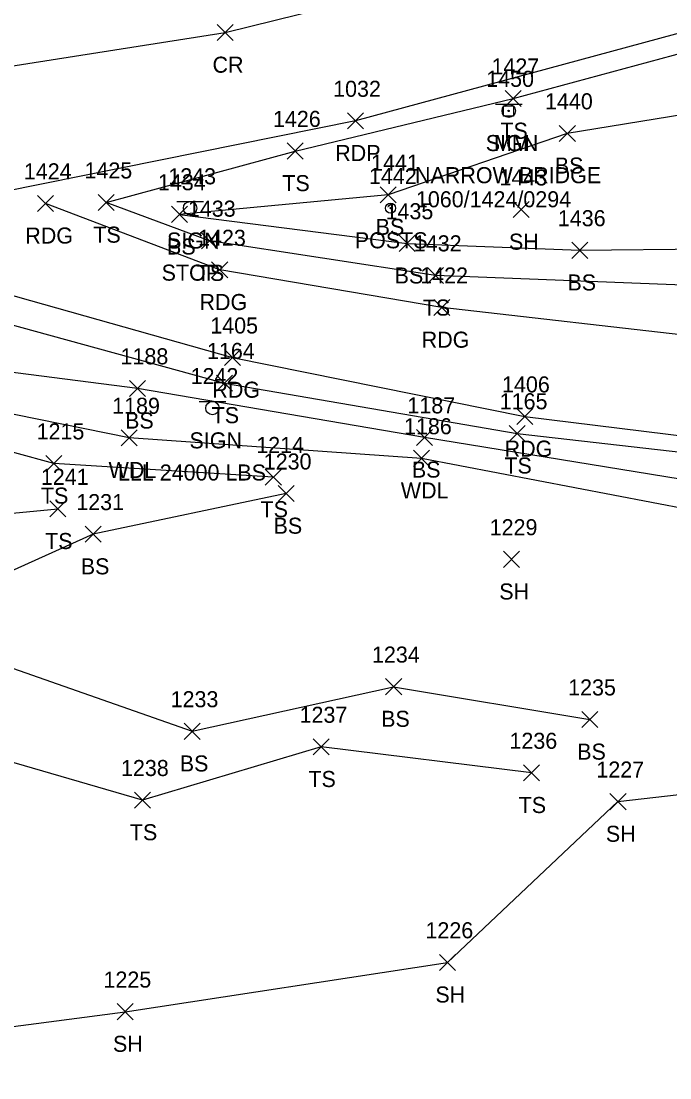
# Model space of a CAD drawing. Extents: x 1633660 to 1636532, y 388643 to 392631.
# Drawn here: x 1633994.3 to 1634075.1, y 388650.9 to 388782.5 of the extents above; entities that cross this region are included whole.
import ezdxf

# ---------------------------------------------------------------- set-up
doc = ezdxf.new("R2010")
doc.units = 0
for name, color, linetype in [('L_A', 7, 'Continuous'), ('L_I', 7, 'Continuous'), ('L_TIC', 7, 'Continuous'), ('LAWA', 7, 'Continuous'), ('LELB', 7, 'Continuous'), ('LPST', 7, 'Continuous'), ('LSOGP', 7, 'Continuous'), ('P_A', 7, 'Continuous'), ('P_I', 7, 'Continuous'), ('P_TIC', 7, 'Continuous'), ('PET', 7, 'Continuous'), ('PEU', 7, 'Continuous'), ('PRC', 7, 'Continuous'), ('S_A', 7, 'Continuous'), ('S_C', 7, 'Continuous'), ('S_I', 7, 'Continuous'), ('SRM', 7, 'Continuous'), ('SSGN', 7, 'Continuous')]:
    doc.layers.add(name, color=color, linetype=linetype)

msp = doc.modelspace()

# ---------------------------------------------------------------- linework, layer by layer
at = {"layer": 'L_TIC'}
for points in [[(1634054.55, 388771.84), (1634056.55, 388773.84)], [(1634056.55, 388771.84), (1634054.55, 388773.84)], [(1634061.3, 388767.5), (1634063.3, 388769.5)], [(1634063.3, 388767.5), (1634061.3, 388769.5)], [(1634027.39, 388765.31), (1634029.39, 388767.31)], [(1634029.39, 388765.31), (1634027.39, 388767.31)], [(1634038.99, 388759.86), (1634040.99, 388761.86)], [(1634040.99, 388759.86), (1634038.99, 388761.86)], [(1634003.85, 388758.89), (1634005.85, 388760.89)], [(1634005.85, 388758.89), (1634003.85, 388760.89)], [(1634013, 388757.42), (1634015, 388759.42)], [(1634015, 388757.42), (1634013, 388759.42)], [(1634055.54, 388758.02), (1634057.54, 388760.02)], [(1634057.54, 388758.02), (1634055.54, 388760.02)], [(1634016.74, 388754.13), (1634018.74, 388756.13)], [(1634018.74, 388754.13), (1634016.74, 388756.13)], [(1634041.35, 388753.81), (1634043.35, 388755.81)], [(1634043.35, 388753.81), (1634041.35, 388755.81)], [(1634062.87, 388752.94), (1634064.87, 388754.94)], [(1634064.87, 388752.94), (1634062.87, 388754.94)], [(1634044.88, 388749.81), (1634046.88, 388751.81)], [(1634046.88, 388749.81), (1634044.88, 388751.81)], [(1634018.59, 388736.41), (1634020.59, 388738.41)], [(1634020.59, 388736.41), (1634018.59, 388738.41)], [(1634007.78, 388735.74), (1634009.78, 388737.74)], [(1634009.78, 388735.74), (1634007.78, 388737.74)], [(1634006.74, 388729.58), (1634008.74, 388731.58)], [(1634008.74, 388729.58), (1634006.74, 388731.58)], [(1634043.5, 388729.63), (1634045.5, 388731.63)], [(1634045.5, 388729.63), (1634043.5, 388731.63)], [(1634055.05, 388730.14), (1634057.05, 388732.14)], [(1634057.05, 388730.14), (1634055.05, 388732.14)], [(1634043.14, 388727.03), (1634045.14, 388729.03)], [(1634045.14, 388727.03), (1634043.14, 388729.03)], [(1633997.33, 388726.39), (1633999.33, 388728.39)], [(1633999.33, 388726.39), (1633997.33, 388728.39)], [(1634024.68, 388724.69), (1634026.68, 388726.69)], [(1634026.68, 388724.69), (1634024.68, 388726.69)], [(1634026.27, 388722.64), (1634028.27, 388724.64)], [(1634028.27, 388722.64), (1634026.27, 388724.64)], [(1633997.85, 388720.73), (1633999.85, 388722.73)], [(1633999.85, 388720.73), (1633997.85, 388722.73)], [(1634002.26, 388717.58), (1634004.26, 388719.58)], [(1634004.26, 388717.58), (1634002.26, 388719.58)], [(1634054.33, 388714.45), (1634056.33, 388716.45)], [(1634056.33, 388714.45), (1634054.33, 388716.45)], [(1634039.67, 388698.59), (1634041.67, 388700.59)], [(1634041.67, 388698.59), (1634039.67, 388700.59)], [(1634064.09, 388694.5), (1634066.09, 388696.5)], [(1634066.09, 388694.5), (1634064.09, 388696.5)], [(1634014.59, 388693.03), (1634016.59, 388695.03)], [(1634016.59, 388693.03), (1634014.59, 388695.03)], [(1634030.65, 388691.09), (1634032.65, 388693.09)], [(1634032.65, 388691.09), (1634030.65, 388693.09)], [(1634056.83, 388687.85), (1634058.83, 388689.85)], [(1634058.83, 388687.85), (1634056.83, 388689.85)], [(1634008.4, 388684.46), (1634010.4, 388686.46)], [(1634010.4, 388684.46), (1634008.4, 388686.46)], [(1634067.61, 388684.27), (1634069.61, 388686.27)], [(1634069.61, 388684.27), (1634067.61, 388686.27)], [(1634046.38, 388664.25), (1634048.38, 388666.25)], [(1634048.38, 388664.25), (1634046.38, 388666.25)], [(1634006.22, 388658.11), (1634008.22, 388660.11)], [(1634008.22, 388658.11), (1634006.22, 388660.11)]]:
    msp.add_lwpolyline(points, dxfattribs=at)
at = {"layer": 'LAWA'}
msp.add_lwpolyline([(1634213.54, 388715.93), (1634181.29, 388718.06), (1634158.57, 388709.96), (1634132.08, 388702.35), (1634126.3, 388716.32), (1634107.18, 388718.38), (1634087.11, 388719.77), (1634044.14, 388728.03), (1634007.74, 388730.58), (1633979.24, 388736.34), (1633973.65, 388737.75)], dxfattribs=at)
at = {"layer": 'LELB'}
for points in [[(1634004.85, 388759.89), (1634028.39, 388766.31), (1634055.55, 388772.84), (1634087.81, 388781.56), (1634094.13, 388773.43), (1634095.58, 388760.67), (1634083.14, 388749.36), (1634045.88, 388750.81), (1634017.74, 388755.13)], [(1634014, 388758.42), (1634042.35, 388754.81), (1634063.87, 388753.94), (1634079.68, 388754.14), (1634090.31, 388767.38), (1634089.57, 388772.95), (1634062.3, 388768.5), (1634039.99, 388760.86)], [(1634039.99, 388760.86), (1634014, 388758.42)], [(1634017.74, 388755.13), (1634004.85, 388759.89)], [(1633929.25, 388734.22), (1633932.64, 388741.33), (1633934.84, 388748.14), (1633955.61, 388748.95), (1633990.07, 388745.5), (1634019.59, 388737.41), (1634056.05, 388731.14), (1634102.32, 388725.85), (1634131.53, 388723.22), (1634169.63, 388722.22), (1634213.51, 388722.74)], [(1634103.78, 388721.69), (1634089.59, 388723.27), (1634044.5, 388730.63), (1634008.78, 388736.74), (1633974.13, 388741.19), (1633971.98, 388741.19), (1633967.26, 388742.03), (1633963.35, 388743.2), (1633950.4, 388742.79), (1633939.89, 388743.26), (1633938.77, 388738.1), (1633951.99, 388740.33), (1633960.06, 388738.71)], [(1634025.68, 388725.69), (1633998.33, 388727.39), (1633974.03, 388734.05)], [(1634027.27, 388723.64), (1634003.26, 388718.58), (1633978, 388707.19), (1634015.59, 388694.03), (1634040.67, 388699.59), (1634065.09, 388695.5)], [(1633971.87, 388719.16), (1633998.85, 388721.73)], [(1634057.83, 388688.85), (1634031.65, 388692.09), (1634009.4, 388685.46), (1633973.11, 388696)]]:
    msp.add_lwpolyline(points, dxfattribs=at)
at = {"layer": 'LPST'}
for radius in [0.625, 0.0833]:
    msp.add_circle((1634040.29, 388759.19), radius, dxfattribs=at)
at = {"layer": 'LSOGP'}
msp.add_lwpolyline([(1633892.15, 388670.64), (1633924.06, 388658.35), (1633934.83, 388655.28), (1633940.09, 388658.82), (1633943.21, 388657.8), (1633944.44, 388650.87), (1634007.22, 388659.11), (1634047.38, 388665.25), (1634068.61, 388685.27), (1634091.13, 388687.87), (1634119.65, 388686.04), (1634149.89, 388685.18), (1634208.91, 388690.49), (1634214.85, 388708.43), (1634213.54, 388715.93), (1634213.47, 388720.91), (1634213.51, 388722.74), (1634213.85, 388724.5), (1634214.78, 388736.17), (1634218.98, 388740.85), (1634254.67, 388740.24)], dxfattribs=at)
at = {"layer": 'P_TIC'}
for points in [[(1634018.68, 388780.06), (1634020.68, 388782.06)], [(1634020.68, 388780.06), (1634018.68, 388782.06)], [(1634034.91, 388769.06), (1634036.91, 388771.06)], [(1634036.91, 388769.06), (1634034.91, 388771.06)], [(1633996.3, 388758.78), (1633998.3, 388760.78)], [(1633998.3, 388758.78), (1633996.3, 388760.78)], [(1634018, 388750.5), (1634020, 388752.5)], [(1634020, 388750.5), (1634018, 388752.5)], [(1634045.67, 388745.81), (1634047.67, 388747.81)], [(1634047.67, 388745.81), (1634045.67, 388747.81)], [(1634019.6, 388739.58), (1634021.6, 388741.58)], [(1634021.6, 388739.58), (1634019.6, 388741.58)], [(1634056, 388732.24), (1634058, 388734.24)], [(1634058, 388732.24), (1634056, 388734.24)]]:
    msp.add_lwpolyline(points, dxfattribs=at)
at = {"layer": 'PET'}
msp.add_lwpolyline([(1634233.66, 388838.29), (1634176.14, 388816.11), (1634127.42, 388797.4), (1634083.73, 388783.04), (1634035.91, 388770.06), (1633987.08, 388760.24), (1633936.49, 388754.34), (1633886.38, 388755.37), (1633827.16, 388754.09), (1633779.6, 388750.43), (1633734.35, 388742.35), (1633709.35, 388735.6), (1633689.74, 388728.83)], dxfattribs=at)
at = {"layer": 'PEU'}
for points in [[(1634091.6, 388782.99), (1634098.82, 388773.22), (1634098.99, 388759.29), (1634089.45, 388746.89), (1634079.35, 388743.09), (1634046.67, 388746.81), (1634019, 388751.5), (1633997.3, 388759.78)], [(1633965.07, 388753.44), (1633990.25, 388749.16), (1634020.6, 388740.58), (1634057, 388733.24), (1634101.12, 388727.81), (1634139.19, 388724.39), (1634181.63, 388724.18), (1634213.85, 388724.5)]]:
    msp.add_lwpolyline(points, dxfattribs=at)
at = {"layer": 'PRC'}
msp.add_lwpolyline([(1633685.21, 388740.89), (1633722.47, 388753.09), (1633765.95, 388761.74), (1633808.84, 388766.45), (1633860.63, 388768.05), (1633911.93, 388769.08), (1633965.45, 388772.58), (1634019.68, 388781.06), (1634071.37, 388793.87), (1634111.14, 388806.36), (1634160.92, 388824.06), (1634207.93, 388842.02), (1634253.71, 388860.36), (1634302.74, 388880.25), (1634347.86, 388899.14), (1634390.05, 388916.89), (1634425.6, 388933.8), (1634443.27, 388943.77), (1634464.46, 388957.57)], dxfattribs=at)
at = {"layer": 'SRM'}
msp.add_lwpolyline([(1634054.35, 388771.92), (1634055.6, 388771.92), (1634055.6, 388770.67), (1634054.35, 388770.67)], close=True, dxfattribs=at)
msp.add_circle((1634054.98, 388771.3), 0.0833, dxfattribs=at)
at = {"layer": 'SSGN'}
for p, q in [((1634053.35, 388772.15), (1634056.69, 388772.15)), ((1634055, 388771.32), (1634055, 388771.32)), ((1634013.66, 388760.01), (1634017, 388760.01)), ((1634015.31, 388759.18), (1634015.31, 388759.18)), ((1634016.45, 388735.12), (1634019.78, 388735.12)), ((1634018.1, 388734.29), (1634018.1, 388734.29))]:
    msp.add_line(p, q, dxfattribs=at)
for centre in [(1634055, 388771.32), (1634015.31, 388759.18), (1634018.1, 388734.29)]:
    msp.add_circle(centre, 0.833, dxfattribs=at)

# ---------------------------------------------------------------- texts
at = {"layer": 'L_A'}
for s, p in [('TS', (1634053.96, 388767.84)), ('BS', (1634060.74, 388763.5)), ('TS', (1634026.8, 388761.31)), ('BS', (1634038.43, 388755.86)), ('TS', (1634003.26, 388754.89)), ('BS', (1634012.44, 388753.42)), ('POSTS', (1634035.83, 388754.19)), ('SH', (1634055.03, 388754.02)), ('TS', (1634016.15, 388750.13)), ('BS', (1634040.79, 388749.81)), ('BS', (1634062.31, 388748.94)), ('TS', (1634044.29, 388745.81)), ('TS', (1634018, 388732.41)), ('BS', (1634007.22, 388731.74)), ('WDL', (1634005.16, 388725.58)), ('BS', (1634042.94, 388725.63)), ('TS', (1634054.46, 388726.14)), ('WDL', (1634041.56, 388723.03)), ('TS', (1633996.74, 388722.39)), ('TS', (1634024.09, 388720.69)), ('BS', (1634025.71, 388718.64)), ('TS', (1633997.26, 388716.73)), ('BS', (1634001.7, 388713.58)), ('SH', (1634053.82, 388710.45)), ('BS', (1634039.11, 388694.59)), ('BS', (1634063.53, 388690.5)), ('BS', (1634014.03, 388689.03)), ('TS', (1634030.05, 388687.09)), ('TS', (1634056.24, 388683.85)), ('TS', (1634007.81, 388680.46)), ('SH', (1634067.1, 388680.27)), ('SH', (1634045.87, 388660.25)), ('SH', (1634005.71, 388654.11))]:
    msp.add_text(s, height=2, dxfattribs=at).set_placement(p)
at = {"layer": 'L_I'}
for s, p in [('1427', (1634052.85, 388775.84)), ('1440', (1634059.52, 388771.5)), ('1426', (1634025.64, 388769.31)), ('1441', (1634037.86, 388763.86)), ('1425', (1634002.16, 388762.89)), ('1434', (1634011.31, 388761.42)), ('1442', (1634037.59, 388762.19)), ('1443', (1634053.85, 388762.02)), ('1433', (1634015.04, 388758.13)), ('1435', (1634039.66, 388757.81)), ('1436', (1634061.12, 388756.94)), ('1432', (1634043.18, 388753.81)), ('1164', (1634017.42, 388740.41)), ('1188', (1634006.65, 388739.74)), ('1189', (1634005.61, 388733.58)), ('1187', (1634042.38, 388733.63)), ('1165', (1634053.88, 388734.14)), ('1186', (1634041.96, 388731.03)), ('1215', (1633996.2, 388730.39)), ('1214', (1634023.56, 388728.69)), ('1230', (1634024.49, 388726.64)), ('1241', (1633996.73, 388724.73)), ('1231', (1634001.14, 388721.58)), ('1229', (1634052.63, 388718.45)), ('1234', (1634037.97, 388702.59)), ('1235', (1634062.4, 388698.5)), ('1233', (1634012.89, 388697.03)), ('1237', (1634028.95, 388695.09)), ('1236', (1634055.09, 388691.85)), ('1238', (1634006.71, 388688.46)), ('1227', (1634065.92, 388688.27)), ('1226', (1634044.63, 388668.25)), ('1225', (1634004.53, 388662.11))]:
    msp.add_text(s, height=2, dxfattribs=at).set_placement(p)
at = {"layer": 'P_A'}
for s, p in [('CR', (1634018.11, 388776.06)), ('RDP', (1634033.39, 388765.06)), ('RDG', (1633994.79, 388754.78)), ('RDG', (1634016.49, 388746.5)), ('RDG', (1634044.16, 388741.81)), ('RDG', (1634018.09, 388735.58)), ('RDG', (1634054.49, 388728.24))]:
    msp.add_text(s, height=2, dxfattribs=at).set_placement(p)
at = {"layer": 'P_I'}
for s, p in [('1032', (1634033.13, 388773.06)), ('1424', (1633994.61, 388762.78)), ('1423', (1634016.31, 388754.5)), ('1422', (1634043.98, 388749.81)), ('1405', (1634017.83, 388743.58)), ('1406', (1634054.17, 388736.24))]:
    msp.add_text(s, height=2, dxfattribs=at).set_placement(p)
at = {"layer": 'S_A'}
for s, p in [('SIGN', (1634052.14, 388766.3)), ('MM', (1634053.17, 388766.3)), ('SIGN', (1634012.45, 388754.16)), ('SIGN', (1634015.24, 388729.27))]:
    msp.add_text(s, height=2, dxfattribs=at).set_placement(p)
at = {"layer": 'S_C'}
for s, p in [('NARROW BRIDGE', (1634043.33, 388762.3)), ('1060/1424/0294', (1634043.44, 388759.3)), ('STOP', (1634011.77, 388750.16)), ('LLL 24000 LBS', (1634006.33, 388725.27))]:
    msp.add_text(s, height=2, dxfattribs=at).set_placement(p)
at = {"layer": 'S_I'}
for s, p in [('1450', (1634052.2, 388774.3)), ('1450', (1634052.2, 388774.3)), ('1243', (1634012.6, 388762.16)), ('1242', (1634015.38, 388737.27))]:
    msp.add_text(s, height=2, dxfattribs=at).set_placement(p)

doc.saveas('drawing.dxf')
